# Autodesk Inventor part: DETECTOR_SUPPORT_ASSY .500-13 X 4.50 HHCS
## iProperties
Shininess: 64.0
Length Units: 11272
Angle Units: 11279
Time Units: 11290
Mass Units: 11286
Length Display Precision: 3
Angle Display Precision: 2
Compacted: True
Part Number: DETECTOR_SUPPORT_ASSY .500-13 X 4.50 HHCS
Document SubType Name: Modeling
Created: 2004-08
Designer: John Blackburn
Material: MILD_STEEL
Manufacturer: Standard
Standards Organization: Custom
Density: 0.0
Volumn: 0.0
Area: 0.0
PropertySet Name: Model Information
Control State: 0
Master: False
Checked Out: False
Author: John Blackburn
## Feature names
1. Base1
